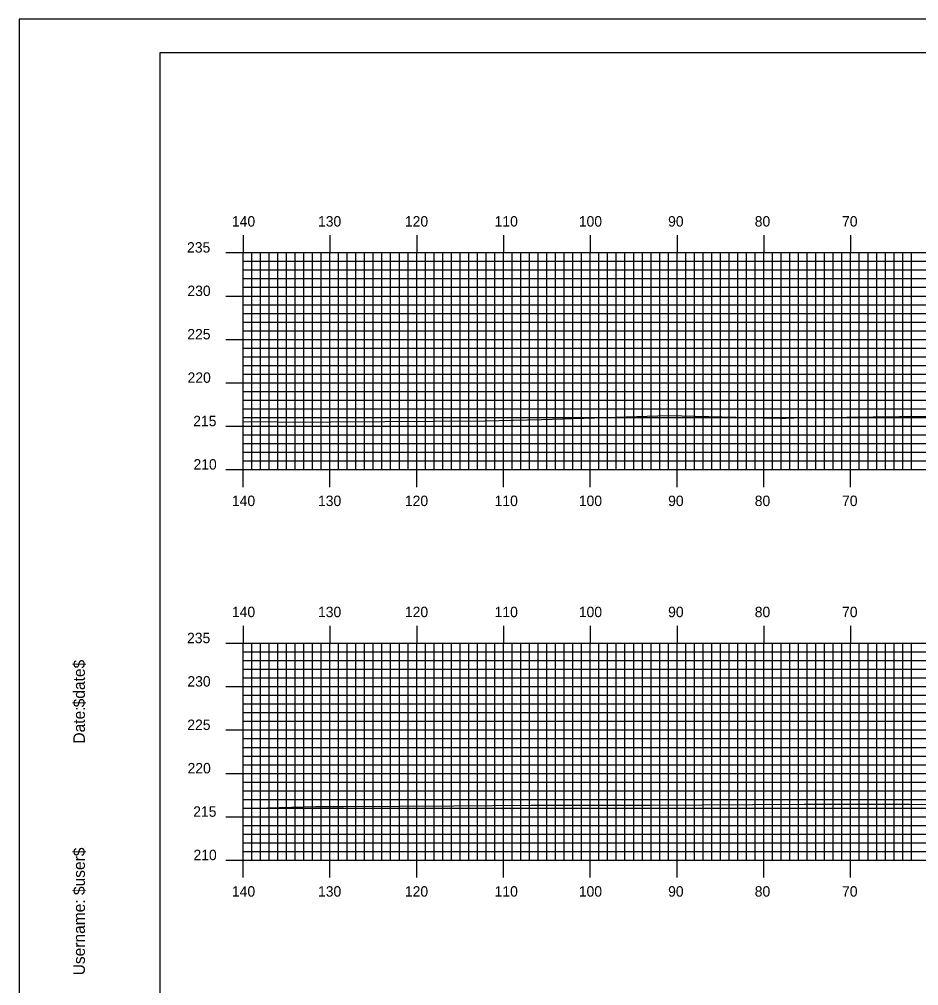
# Model space of a CAD drawing. Extents: x 1818850 to 1819194, y 442591 to 442811.
# Drawn here: x 1818850.4 to 1818954, y 442699.2 to 442810.5 of the extents above; entities that cross this region are included whole.
import ezdxf

# ---------------------------------------------------------------- set-up
doc = ezdxf.new("R2010")
doc.units = 0
for name, color, linetype in [('BORDER', 7, 'Continuous'), ('H_V ANNOTATION', 7, 'Continuous'), ('MAJOR', 7, 'Continuous'), ('MINOR', 7, 'Continuous'), ('PLOT BOUNDARY', 7, 'Continuous'), ('S_Roadway_Centerline', 7, 'Continuous')]:
    doc.layers.add(name, color=color, linetype=linetype)

msp = doc.modelspace()

# ---------------------------------------------------------------- linework, layer by layer
at = {"layer": 'BORDER'}
msp.add_lwpolyline([(1818866.55, 442596.67), (1819186.55, 442596.67), (1819186.55, 442806.67), (1818866.55, 442806.67)], close=True, dxfattribs=at)
at = {"layer": 'MAJOR'}
for p, q in [((1818876.15, 442785.67), (1818876.15, 442783.67)), ((1818886.15, 442785.67), (1818886.15, 442783.67)), ((1818896.15, 442785.67), (1818896.15, 442783.67)), ((1818906.15, 442785.67), (1818906.15, 442783.67)), ((1818916.15, 442785.67), (1818916.15, 442783.67)), ((1818926.15, 442785.67), (1818926.15, 442783.67)), ((1818936.15, 442785.67), (1818936.15, 442783.67)), ((1818946.15, 442785.67), (1818946.15, 442783.67)), ((1818874.15, 442783.67), (1818876.15, 442783.67)), ((1818876.15, 442783.67), (1819156.15, 442783.67)), ((1818876.15, 442758.67), (1818876.15, 442783.67)), ((1818876.15, 442758.67), (1818876.15, 442783.67)), ((1818876.15, 442783.67), (1819156.15, 442783.67)), ((1818886.15, 442758.67), (1818886.15, 442783.67)), ((1818896.15, 442758.67), (1818896.15, 442783.67)), ((1818906.15, 442758.67), (1818906.15, 442783.67)), ((1818916.15, 442758.67), (1818916.15, 442783.67)), ((1818926.15, 442758.67), (1818926.15, 442783.67)), ((1818936.15, 442758.67), (1818936.15, 442783.67)), ((1818946.15, 442758.67), (1818946.15, 442783.67)), ((1818874.15, 442778.67), (1818876.15, 442778.67)), ((1818876.15, 442778.67), (1819156.15, 442778.67)), ((1818874.15, 442773.67), (1818876.15, 442773.67)), ((1818876.15, 442773.67), (1819156.15, 442773.67)), ((1818874.15, 442768.67), (1818876.15, 442768.67)), ((1818876.15, 442768.67), (1819156.15, 442768.67)), ((1818874.15, 442763.67), (1818876.15, 442763.67)), ((1818876.15, 442763.67), (1819156.15, 442763.67)), ((1818874.15, 442758.67), (1818876.15, 442758.67)), ((1818876.15, 442758.67), (1819156.15, 442758.67)), ((1818876.15, 442758.67), (1819156.15, 442758.67)), ((1818876.15, 442756.66), (1818876.15, 442758.67)), ((1818886.15, 442756.66), (1818886.15, 442758.67)), ((1818896.15, 442756.66), (1818896.15, 442758.67)), ((1818906.15, 442756.66), (1818906.15, 442758.67)), ((1818916.15, 442756.66), (1818916.15, 442758.67)), ((1818926.15, 442756.66), (1818926.15, 442758.67)), ((1818936.15, 442756.66), (1818936.15, 442758.67)), ((1818946.15, 442756.66), (1818946.15, 442758.67)), ((1818876.15, 442740.67), (1818876.15, 442738.67)), ((1818886.15, 442740.67), (1818886.15, 442738.67)), ((1818896.15, 442740.67), (1818896.15, 442738.67)), ((1818906.15, 442740.67), (1818906.15, 442738.67)), ((1818916.15, 442740.67), (1818916.15, 442738.67)), ((1818926.15, 442740.67), (1818926.15, 442738.67)), ((1818936.15, 442740.67), (1818936.15, 442738.67)), ((1818946.15, 442740.67), (1818946.15, 442738.67)), ((1818874.15, 442738.67), (1818876.15, 442738.67)), ((1818876.15, 442738.67), (1819156.15, 442738.67)), ((1818876.15, 442713.67), (1818876.15, 442738.67)), ((1818876.15, 442713.67), (1818876.15, 442738.67)), ((1818876.15, 442738.67), (1819156.15, 442738.67)), ((1818886.15, 442713.67), (1818886.15, 442738.67)), ((1818896.15, 442713.67), (1818896.15, 442738.67)), ((1818906.15, 442713.67), (1818906.15, 442738.67)), ((1818916.15, 442713.67), (1818916.15, 442738.67)), ((1818926.15, 442713.67), (1818926.15, 442738.67)), ((1818936.15, 442713.67), (1818936.15, 442738.67)), ((1818946.15, 442713.67), (1818946.15, 442738.67)), ((1818874.15, 442733.67), (1818876.15, 442733.67)), ((1818876.15, 442733.67), (1819156.15, 442733.67)), ((1818874.15, 442728.67), (1818876.15, 442728.67)), ((1818876.15, 442728.67), (1819156.15, 442728.67)), ((1818874.15, 442723.67), (1818876.15, 442723.67)), ((1818876.15, 442723.67), (1819156.15, 442723.67)), ((1818874.15, 442718.67), (1818876.15, 442718.67)), ((1818876.15, 442718.67), (1819156.15, 442718.67)), ((1818874.15, 442713.67), (1818876.15, 442713.67)), ((1818876.15, 442713.67), (1819156.15, 442713.67)), ((1818876.15, 442713.67), (1819156.15, 442713.67)), ((1818876.15, 442711.66), (1818876.15, 442713.67)), ((1818886.15, 442711.66), (1818886.15, 442713.67)), ((1818896.15, 442711.66), (1818896.15, 442713.67)), ((1818906.15, 442711.66), (1818906.15, 442713.67)), ((1818916.15, 442711.66), (1818916.15, 442713.67)), ((1818926.15, 442711.66), (1818926.15, 442713.67)), ((1818936.15, 442711.66), (1818936.15, 442713.67)), ((1818946.15, 442711.66), (1818946.15, 442713.67))]:
    msp.add_line(p, q, dxfattribs=at)
at = {"layer": 'MINOR'}
for p, q in [((1818877.15, 442758.67), (1818877.15, 442783.67)), ((1818878.15, 442758.67), (1818878.15, 442783.67)), ((1818879.15, 442758.67), (1818879.15, 442783.67)), ((1818880.15, 442758.67), (1818880.15, 442783.67)), ((1818881.15, 442758.67), (1818881.15, 442783.67)), ((1818882.15, 442758.67), (1818882.15, 442783.67)), ((1818883.15, 442758.67), (1818883.15, 442783.67)), ((1818884.15, 442758.67), (1818884.15, 442783.67)), ((1818885.15, 442758.67), (1818885.15, 442783.67)), ((1818887.15, 442758.67), (1818887.15, 442783.67)), ((1818888.15, 442758.67), (1818888.15, 442783.67)), ((1818889.15, 442758.67), (1818889.15, 442783.67)), ((1818890.15, 442758.67), (1818890.15, 442783.67)), ((1818891.15, 442758.67), (1818891.15, 442783.67)), ((1818892.15, 442758.67), (1818892.15, 442783.67)), ((1818893.15, 442758.67), (1818893.15, 442783.67)), ((1818894.15, 442758.67), (1818894.15, 442783.67)), ((1818895.15, 442758.67), (1818895.15, 442783.67)), ((1818897.15, 442758.67), (1818897.15, 442783.67)), ((1818898.15, 442758.67), (1818898.15, 442783.67)), ((1818899.15, 442758.67), (1818899.15, 442783.67)), ((1818900.15, 442758.67), (1818900.15, 442783.67)), ((1818901.15, 442758.67), (1818901.15, 442783.67)), ((1818902.15, 442758.67), (1818902.15, 442783.67)), ((1818903.15, 442758.67), (1818903.15, 442783.67)), ((1818904.15, 442758.67), (1818904.15, 442783.67)), ((1818905.15, 442758.67), (1818905.15, 442783.67)), ((1818907.15, 442758.67), (1818907.15, 442783.67)), ((1818908.15, 442758.67), (1818908.15, 442783.67)), ((1818909.15, 442758.67), (1818909.15, 442783.67)), ((1818910.15, 442758.67), (1818910.15, 442783.67)), ((1818911.15, 442758.67), (1818911.15, 442783.67)), ((1818912.15, 442758.67), (1818912.15, 442783.67)), ((1818913.15, 442758.67), (1818913.15, 442783.67)), ((1818914.15, 442758.67), (1818914.15, 442783.67)), ((1818915.15, 442758.67), (1818915.15, 442783.67)), ((1818917.15, 442758.67), (1818917.15, 442783.67)), ((1818918.15, 442758.67), (1818918.15, 442783.67)), ((1818919.15, 442758.67), (1818919.15, 442783.67)), ((1818920.15, 442758.67), (1818920.15, 442783.67)), ((1818921.15, 442758.67), (1818921.15, 442783.67)), ((1818922.15, 442758.67), (1818922.15, 442783.67)), ((1818923.15, 442758.67), (1818923.15, 442783.67)), ((1818924.15, 442758.67), (1818924.15, 442783.67)), ((1818925.15, 442758.67), (1818925.15, 442783.67)), ((1818927.15, 442758.67), (1818927.15, 442783.67)), ((1818928.15, 442758.67), (1818928.15, 442783.67)), ((1818929.15, 442758.67), (1818929.15, 442783.67)), ((1818930.15, 442758.67), (1818930.15, 442783.67)), ((1818931.15, 442758.67), (1818931.15, 442783.67)), ((1818932.15, 442758.67), (1818932.15, 442783.67)), ((1818933.15, 442758.67), (1818933.15, 442783.67)), ((1818934.15, 442758.67), (1818934.15, 442783.67)), ((1818935.15, 442758.67), (1818935.15, 442783.67)), ((1818937.15, 442758.67), (1818937.15, 442783.67)), ((1818938.15, 442758.67), (1818938.15, 442783.67)), ((1818939.15, 442758.67), (1818939.15, 442783.67)), ((1818940.15, 442758.67), (1818940.15, 442783.67)), ((1818941.15, 442758.67), (1818941.15, 442783.67)), ((1818942.15, 442758.67), (1818942.15, 442783.67)), ((1818943.15, 442758.67), (1818943.15, 442783.67)), ((1818944.15, 442758.67), (1818944.15, 442783.67)), ((1818945.15, 442758.67), (1818945.15, 442783.67)), ((1818947.15, 442758.67), (1818947.15, 442783.67)), ((1818948.15, 442758.67), (1818948.15, 442783.67)), ((1818949.15, 442758.67), (1818949.15, 442783.67)), ((1818950.15, 442758.67), (1818950.15, 442783.67)), ((1818951.15, 442758.67), (1818951.15, 442783.67)), ((1818952.15, 442758.67), (1818952.15, 442783.67)), ((1818953.15, 442758.67), (1818953.15, 442783.67)), ((1818876.15, 442782.67), (1819156.15, 442782.67)), ((1818876.15, 442782.67), (1818878.16, 442782.67)), ((1818876.15, 442781.67), (1819156.15, 442781.67)), ((1818876.15, 442781.67), (1818878.16, 442781.67)), ((1818876.15, 442780.67), (1819156.15, 442780.67)), ((1818876.15, 442780.67), (1818878.16, 442780.67)), ((1818876.15, 442779.67), (1819156.15, 442779.67)), ((1818876.15, 442779.67), (1818878.16, 442779.67)), ((1818876.15, 442777.67), (1819156.15, 442777.67)), ((1818876.15, 442777.67), (1818878.16, 442777.67)), ((1818876.15, 442776.67), (1819156.15, 442776.67)), ((1818876.15, 442776.67), (1818878.16, 442776.67)), ((1818876.15, 442775.67), (1819156.15, 442775.67)), ((1818876.15, 442775.67), (1818878.16, 442775.67)), ((1818876.15, 442774.67), (1819156.15, 442774.67)), ((1818876.15, 442774.67), (1818878.16, 442774.67)), ((1818876.15, 442772.67), (1819156.15, 442772.67)), ((1818876.15, 442772.67), (1818878.16, 442772.67)), ((1818876.15, 442771.67), (1819156.15, 442771.67)), ((1818876.15, 442771.67), (1818878.16, 442771.67)), ((1818876.15, 442770.67), (1819156.15, 442770.67)), ((1818876.15, 442770.67), (1818878.16, 442770.67)), ((1818876.15, 442769.67), (1819156.15, 442769.67)), ((1818876.15, 442769.67), (1818878.16, 442769.67)), ((1818876.15, 442767.67), (1819156.15, 442767.67)), ((1818876.15, 442767.67), (1818878.16, 442767.67)), ((1818876.15, 442766.67), (1819156.15, 442766.67)), ((1818876.15, 442766.67), (1818878.16, 442766.67)), ((1818876.15, 442765.67), (1819156.15, 442765.67)), ((1818876.15, 442765.67), (1818878.16, 442765.67)), ((1818876.15, 442764.67), (1819156.15, 442764.67)), ((1818876.15, 442764.67), (1818878.16, 442764.67)), ((1818876.15, 442762.67), (1819156.15, 442762.67)), ((1818876.15, 442762.67), (1818878.16, 442762.67)), ((1818876.15, 442761.67), (1819156.15, 442761.67)), ((1818876.15, 442761.67), (1818878.16, 442761.67)), ((1818876.15, 442760.67), (1819156.15, 442760.67)), ((1818876.15, 442760.67), (1818878.16, 442760.67)), ((1818876.15, 442759.67), (1819156.15, 442759.67)), ((1818876.15, 442759.67), (1818878.16, 442759.67)), ((1818877.15, 442713.67), (1818877.15, 442738.67)), ((1818878.15, 442713.67), (1818878.15, 442738.67)), ((1818879.15, 442713.67), (1818879.15, 442738.67)), ((1818880.15, 442713.67), (1818880.15, 442738.67)), ((1818881.15, 442713.67), (1818881.15, 442738.67)), ((1818882.15, 442713.67), (1818882.15, 442738.67)), ((1818883.15, 442713.67), (1818883.15, 442738.67)), ((1818884.15, 442713.67), (1818884.15, 442738.67)), ((1818885.15, 442713.67), (1818885.15, 442738.67)), ((1818887.15, 442713.67), (1818887.15, 442738.67)), ((1818888.15, 442713.67), (1818888.15, 442738.67)), ((1818889.15, 442713.67), (1818889.15, 442738.67)), ((1818890.15, 442713.67), (1818890.15, 442738.67)), ((1818891.15, 442713.67), (1818891.15, 442738.67)), ((1818892.15, 442713.67), (1818892.15, 442738.67)), ((1818893.15, 442713.67), (1818893.15, 442738.67)), ((1818894.15, 442713.67), (1818894.15, 442738.67)), ((1818895.15, 442713.67), (1818895.15, 442738.67)), ((1818897.15, 442713.67), (1818897.15, 442738.67)), ((1818898.15, 442713.67), (1818898.15, 442738.67)), ((1818899.15, 442713.67), (1818899.15, 442738.67)), ((1818900.15, 442713.67), (1818900.15, 442738.67)), ((1818901.15, 442713.67), (1818901.15, 442738.67)), ((1818902.15, 442713.67), (1818902.15, 442738.67)), ((1818903.15, 442713.67), (1818903.15, 442738.67)), ((1818904.15, 442713.67), (1818904.15, 442738.67)), ((1818905.15, 442713.67), (1818905.15, 442738.67)), ((1818907.15, 442713.67), (1818907.15, 442738.67)), ((1818908.15, 442713.67), (1818908.15, 442738.67)), ((1818909.15, 442713.67), (1818909.15, 442738.67)), ((1818910.15, 442713.67), (1818910.15, 442738.67)), ((1818911.15, 442713.67), (1818911.15, 442738.67)), ((1818912.15, 442713.67), (1818912.15, 442738.67)), ((1818913.15, 442713.67), (1818913.15, 442738.67)), ((1818914.15, 442713.67), (1818914.15, 442738.67)), ((1818915.15, 442713.67), (1818915.15, 442738.67)), ((1818917.15, 442713.67), (1818917.15, 442738.67)), ((1818918.15, 442713.67), (1818918.15, 442738.67)), ((1818919.15, 442713.67), (1818919.15, 442738.67)), ((1818920.15, 442713.67), (1818920.15, 442738.67)), ((1818921.15, 442713.67), (1818921.15, 442738.67)), ((1818922.15, 442713.67), (1818922.15, 442738.67)), ((1818923.15, 442713.67), (1818923.15, 442738.67)), ((1818924.15, 442713.67), (1818924.15, 442738.67)), ((1818925.15, 442713.67), (1818925.15, 442738.67)), ((1818927.15, 442713.67), (1818927.15, 442738.67)), ((1818928.15, 442713.67), (1818928.15, 442738.67)), ((1818929.15, 442713.67), (1818929.15, 442738.67)), ((1818930.15, 442713.67), (1818930.15, 442738.67)), ((1818931.15, 442713.67), (1818931.15, 442738.67)), ((1818932.15, 442713.67), (1818932.15, 442738.67)), ((1818933.15, 442713.67), (1818933.15, 442738.67)), ((1818934.15, 442713.67), (1818934.15, 442738.67)), ((1818935.15, 442713.67), (1818935.15, 442738.67)), ((1818937.15, 442713.67), (1818937.15, 442738.67)), ((1818938.15, 442713.67), (1818938.15, 442738.67)), ((1818939.15, 442713.67), (1818939.15, 442738.67)), ((1818940.15, 442713.67), (1818940.15, 442738.67)), ((1818941.15, 442713.67), (1818941.15, 442738.67)), ((1818942.15, 442713.67), (1818942.15, 442738.67)), ((1818943.15, 442713.67), (1818943.15, 442738.67)), ((1818944.15, 442713.67), (1818944.15, 442738.67)), ((1818945.15, 442713.67), (1818945.15, 442738.67)), ((1818947.15, 442713.67), (1818947.15, 442738.67)), ((1818948.15, 442713.67), (1818948.15, 442738.67)), ((1818949.15, 442713.67), (1818949.15, 442738.67)), ((1818950.15, 442713.67), (1818950.15, 442738.67)), ((1818951.15, 442713.67), (1818951.15, 442738.67)), ((1818952.15, 442713.67), (1818952.15, 442738.67)), ((1818953.15, 442713.67), (1818953.15, 442738.67)), ((1818876.15, 442737.67), (1819156.15, 442737.67)), ((1818876.15, 442737.67), (1818878.16, 442737.67)), ((1818876.15, 442736.67), (1819156.15, 442736.67)), ((1818876.15, 442736.67), (1818878.16, 442736.67)), ((1818876.15, 442735.67), (1819156.15, 442735.67)), ((1818876.15, 442735.67), (1818878.16, 442735.67)), ((1818876.15, 442734.67), (1819156.15, 442734.67)), ((1818876.15, 442734.67), (1818878.16, 442734.67)), ((1818876.15, 442732.67), (1819156.15, 442732.67)), ((1818876.15, 442732.67), (1818878.16, 442732.67)), ((1818876.15, 442731.67), (1819156.15, 442731.67)), ((1818876.15, 442731.67), (1818878.16, 442731.67)), ((1818876.15, 442730.67), (1819156.15, 442730.67)), ((1818876.15, 442730.67), (1818878.16, 442730.67)), ((1818876.15, 442729.67), (1819156.15, 442729.67)), ((1818876.15, 442729.67), (1818878.16, 442729.67)), ((1818876.15, 442727.67), (1819156.15, 442727.67)), ((1818876.15, 442727.67), (1818878.16, 442727.67)), ((1818876.15, 442726.67), (1819156.15, 442726.67)), ((1818876.15, 442726.67), (1818878.16, 442726.67)), ((1818876.15, 442725.67), (1819156.15, 442725.67)), ((1818876.15, 442725.67), (1818878.16, 442725.67)), ((1818876.15, 442724.67), (1819156.15, 442724.67)), ((1818876.15, 442724.67), (1818878.16, 442724.67)), ((1818876.15, 442722.67), (1819156.15, 442722.67)), ((1818876.15, 442722.67), (1818878.16, 442722.67)), ((1818876.15, 442721.67), (1819156.15, 442721.67)), ((1818876.15, 442721.67), (1818878.16, 442721.67)), ((1818876.15, 442720.67), (1819156.15, 442720.67)), ((1818876.15, 442720.67), (1818878.16, 442720.67)), ((1818876.15, 442719.67), (1819156.15, 442719.67)), ((1818876.15, 442719.67), (1818878.16, 442719.67)), ((1818876.15, 442717.67), (1819156.15, 442717.67)), ((1818876.15, 442717.67), (1818878.16, 442717.67)), ((1818876.15, 442716.67), (1819156.15, 442716.67)), ((1818876.15, 442716.67), (1818878.16, 442716.67)), ((1818876.15, 442715.67), (1819156.15, 442715.67)), ((1818876.15, 442715.67), (1818878.16, 442715.67)), ((1818876.15, 442714.67), (1819156.15, 442714.67)), ((1818876.15, 442714.67), (1818878.16, 442714.67))]:
    msp.add_line(p, q, dxfattribs=at)
at = {"layer": 'PLOT BOUNDARY'}
msp.add_lwpolyline([(1818850.36, 442590.55), (1819190.36, 442590.55), (1819190.36, 442810.55), (1818850.36, 442810.55)], close=True, dxfattribs=at)
at = {"layer": 'S_Roadway_Centerline'}
for points in [[(1818876.15, 442764.23), (1818884.23, 442764.15), (1818886.24, 442764.19), (1818892.49, 442764.2), (1818904, 442764.28), (1818910.53, 442764.46), (1818921.53, 442764.77), (1818925.13, 442764.92), (1818936.03, 442764.63), (1818938.08, 442764.61), (1818938.68, 442764.59), (1818939.64, 442764.62), (1818954.8, 442764.81)], [(1818876.15, 442719.62), (1818884.53, 442719.84), (1818887.7, 442719.84), (1818900.44, 442719.94), (1818909.33, 442720), (1818923.1, 442719.99), (1818940.8, 442720.11), (1818948.93, 442720.12), (1818952.95, 442720.12), (1818967.5, 442720.05), (1818976.8, 442719.99), (1818985.17, 442719.89), (1819001.76, 442719.77), (1819002.98, 442719.77), (1819004.96, 442719.69), (1819017.83, 442719.31), (1819032.61, 442719.27), (1819052.82, 442720.41), (1819068.74, 442721.96), (1819070.09, 442722.09), (1819098.53, 442725.38)]]:
    msp.add_lwpolyline(points, dxfattribs=at)

# ---------------------------------------------------------------- texts
at = {"layer": 'BORDER'}
for s, p in [('$date$', (1818857.92, 442731.28)), ('Date:', (1818857.92, 442727.1)), ('$user$', (1818857.92, 442709.65)), ('Username:', (1818857.92, 442700.4))]:
    msp.add_text(s, height=1.339, rotation=90, dxfattribs=at).set_placement(p)
at = {"layer": 'H_V ANNOTATION'}
for s, p in [('140', (1818874.86, 442786.67)), ('130', (1818884.78, 442786.67)), ('120', (1818894.79, 442786.67)), ('110', (1818905.13, 442786.67)), ('100', (1818914.83, 442786.67)), ('90', (1818925.12, 442786.67)), ('80', (1818935.1, 442786.67)), ('70', (1818945.16, 442786.67)), ('235', (1818869.69, 442783.67)), ('230', (1818869.73, 442778.67)), ('225', (1818869.72, 442773.67)), ('220', (1818869.75, 442768.67)), ('215', (1818870.4, 442763.67)), ('210', (1818870.43, 442758.67)), ('140', (1818874.86, 442754.47)), ('130', (1818884.78, 442754.47)), ('120', (1818894.79, 442754.47)), ('110', (1818905.13, 442754.47)), ('100', (1818914.83, 442754.47)), ('90', (1818925.12, 442754.47)), ('80', (1818935.1, 442754.47)), ('70', (1818945.16, 442754.47)), ('140', (1818874.86, 442741.67)), ('130', (1818884.78, 442741.67)), ('120', (1818894.79, 442741.67)), ('110', (1818905.13, 442741.67)), ('100', (1818914.83, 442741.67)), ('90', (1818925.12, 442741.67)), ('80', (1818935.1, 442741.67)), ('70', (1818945.16, 442741.67)), ('235', (1818869.69, 442738.67)), ('230', (1818869.73, 442733.67)), ('225', (1818869.72, 442728.67)), ('220', (1818869.75, 442723.67)), ('215', (1818870.4, 442718.67)), ('210', (1818870.43, 442713.67)), ('140', (1818874.86, 442709.47)), ('130', (1818884.78, 442709.47)), ('120', (1818894.79, 442709.47)), ('110', (1818905.13, 442709.47)), ('100', (1818914.83, 442709.47)), ('90', (1818925.12, 442709.47)), ('80', (1818935.1, 442709.47)), ('70', (1818945.16, 442709.47))]:
    msp.add_text(s, height=1.2, dxfattribs=at).set_placement(p)
at = {"layer": 'MAJOR'}
for p in [(1818876.14, 442758.67), (1818876.14, 442713.67)]:
    msp.add_text('-', height=0.012, dxfattribs=at).set_placement(p)

doc.saveas('drawing.dxf')
